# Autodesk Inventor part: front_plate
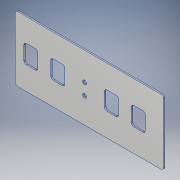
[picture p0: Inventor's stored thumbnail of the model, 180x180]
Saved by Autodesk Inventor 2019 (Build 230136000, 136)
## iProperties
Created: 2018-06
Part Number: front_plate
Material: Aluminum 6061
Document SubType Name: Modeling
Designer: felldings
Density: 2.7 g/cm^3
Appearance: Aluminum - Flat
Mass: 323.602 g
Surface Area: 843.732 cm^2
Volume: 119.853 cm^3
Author: felldings
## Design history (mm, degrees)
sketch "Sketch1"
  geometry: L1 (-160, -70)-(160, -70); L2 (160, -70)-(160, 70); L3 (160, 70)-(-160, 70); L4 (-160, 70)-(-160, -70); L5 (0, -98)-(0, 98) reference; L6 (-224, 0)-(224, 0) reference; 1 further point
  constraints: 8 end point, 2 parallel, 1 horizontal, 1 perpendicular, 2 other
  dimensions: "d0" = 320 distance of L2.end L3.end; "d1" = 140 distance of L1.end L2.end
extrude "plate" new body sketch "Sketch1" distance "d2" = 3; taper "d3" = 0 deg
sketch "Sketch2"
  geometry: L1 (-160, -70)-(160, -70) reference; 3 further points
  dimensions: "d4" = 10 horizontal distance of point (0, 0) point (-10, 10); "d5" = 10 horizontal distance of point (0, 0) point (-10, -15); "d6" = 25 distance of point (-10, 10) point (-10, -15); "d7" = 55 distance from line of L1 point (-10, -15)
hole "mounting_holes" sketch "Sketch2" at (-10, 10), (-10, -15) diameter "d8" = 8.5; stored, may be unused: countersink angle "d12" = 90 deg, drill point angle "d14" = 118 deg; dims "d9" = 6, "d10" = 4, "d11" = 2, "d13" = 8
sketch "Sketch3"
  geometry: L1 (-83, -20)-(-53, -20); L2 (-53, -20)-(-53, 20); L3 (-53, 20)-(-83, 20); L4 (-83, 20)-(-83, -20); L5 (-141, -20)-(-111, -20); L6 (-111, -20)-(-111, 20); L7 (-111, 20)-(-141, 20); L8 (-141, 20)-(-141, -20); L9 (33, -20)-(63, -20); L10 (63, -20)-(63, 20); L11 (63, 20)-(33, 20); L12 (33, 20)-(33, -20); L13 (91, -20)-(121, -20); L14 (121, -20)-(121, 20); L15 (121, 20)-(91, 20); L16 (91, 20)-(91, -20); L17 (-224, 0)-(224, 0) reference; 1 further point
  constraints: 32 end point, 8 parallel, 5 equal length, 4 horizontal, 4 perpendicular, 3 point on line, 1 collinear, 1 other
  dimensions: "d15" = 40 distance of L7.end L5.start; "d16" = 30 distance of L6.end L7.end; "d17" = 83 distance from line of point (0, 0) L4; "d18" = 58 distance between parallel lines of L4 L8; "d19" = 116 distance between parallel lines of L12 L4; "d20" = 58 distance between parallel lines of L14 L10
extrude "Extrusion2" cut sketch "Sketch3" distance "d21" = 3; taper "d22" = 0 deg
fillet "Fillet1" dims "d23" = 5
body "Solid1"
